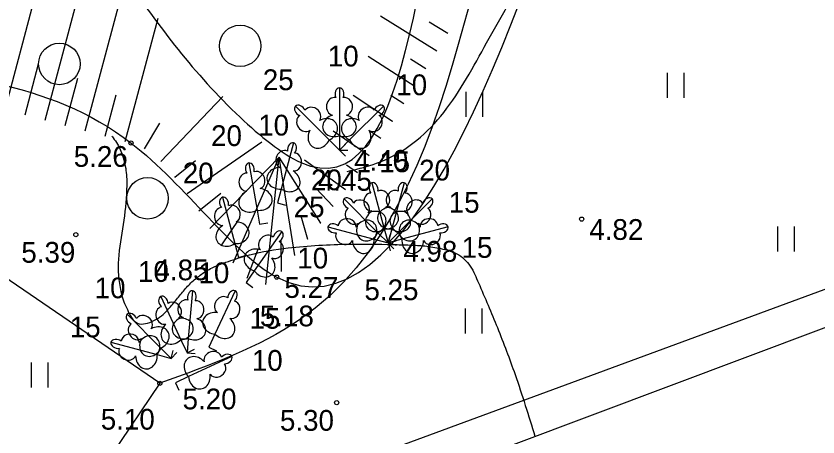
# Model space of a CAD drawing. Extents: x 519536 to 519949, y 326041 to 326519.
# Drawn here: x 519637.13 to 519656.46, y 326374.03 to 326384.17 of the extents above; entities that cross this region are included whole.
import ezdxf

# ---------------------------------------------------------------- set-up
doc = ezdxf.new("R2010")
doc.units = 0
for name, color, linetype in [('NORB_ZOGS_KOKA_####_#', 7, 'Continuous'), ('RAMI_UZMR_####_####_#', 7, 'Continuous'), ('RELJ_AATZ_####_TKST_#', 7, 'Continuous'), ('RELJ_ELEM_####_####_#', 7, 'Continuous'), ('RELJ_HORZ_PAMT_####_#', 7, 'Continuous'), ('RELJ_NOGA_####_####_#', 7, 'Continuous'), ('RELJ_NOGL_####_####_#', 7, 'Continuous'), ('ROBZ_UZMR_####_####_#', 7, 'Continuous'), ('TERT_DIAM_####_TKST_#', 7, 'Continuous'), ('TERT_ELEM_####_####_#', 7, 'Continuous'), ('TERT_KONT_####_####_#', 7, 'Continuous')]:
    doc.layers.add(name, color=color, linetype=linetype)

msp = doc.modelspace()

# ---------------------------------------------------------------- linework, layer by layer
at = {"layer": 'NORB_ZOGS_KOKA_####_#'}
msp.add_line((519640.6, 326375.326), (519637.78, 326371.172), dxfattribs=at)
at = {"layer": 'RAMI_UZMR_####_####_#'}
msp.add_lwpolyline([(519606.503, 326354.123), (519598.183, 326371.842), (519589.598, 326374.981), (519581.568, 326396.559), (519571.96, 326403.209), (519550.477, 326420.838), (519546.03, 326425.168), (519546.311, 326425.748), (519562.267, 326424.735), (519567.537, 326424.176), (519622.695, 326420.6), (519656.101, 326418.428), (519678.291, 326416.771), (519682.862, 326421.74), (519706.678, 326395.86), (519695.81, 326390.264), (519680.586, 326385.663), (519636.229, 326369.014), (519636.521, 326358.648)], dxfattribs=at)
at = {"layer": 'RELJ_ELEM_####_####_#'}
for centre in [(519639.907, 326381.113), (519650.767, 326379.28), (519638.576, 326378.905), (519643.418, 326377.883), (519640.6, 326375.326), (519644.864, 326374.858)]:
    msp.add_circle(centre, 0.05, dxfattribs=at)
at = {"layer": 'RELJ_HORZ_PAMT_####_#'}
for points in [[(519645.113, 326380.427), (519645.346, 326380.483), (519645.975, 326380.684), (519646.793, 326381.18), (519647.446, 326381.851), (519648.477, 326383.527), (519648.984, 326384.426), (519649.237, 326384.877), (519649.497, 326385.324), (519650.138, 326386.146), (519650.938, 326386.852), (519651.383, 326387.175), (519651.83, 326387.466), (519652.729, 326387.645), (519653.8, 326387.311), (519654.871, 326386.904), (519657.011, 326385.952), (519659.155, 326384.951), (519660.229, 326384.485), (519661.305, 326384.067), (519663.623, 326383.243), (519664.796, 326382.875), (519665.984, 326382.554), (519666.875, 326382.387), (519667.774, 326382.257), (519669.587, 326382.105), (519671.035, 326382.078)], [(519639.443, 326381.279), (519639.475, 326381.239), (519639.664, 326380.914), (519639.731, 326380.708), (519639.777, 326380.502), (519639.803, 326380.087), (519639.732, 326379.256), (519639.611, 326378.416), (519639.641, 326377.632), (519639.752, 326377.245), (519639.84, 326377.053), (519639.952, 326376.863), (519640.105, 326376.761), (519640.306, 326376.777), (519640.679, 326376.986), (519640.884, 326377.199), (519641.075, 326377.432), (519641.27, 326377.662), (519641.488, 326377.865), (519641.72, 326378.033)], [(519641.72, 326378.033), (519641.859, 326378.107), (519642.309, 326378.281), (519642.763, 326378.419), (519643.691, 326378.586), (519645.169, 326378.677), (519646.214, 326378.669), (519646.631, 326378.655)], [(519646.631, 326378.655), (519646.989, 326378.634), (519647.374, 326378.57), (519647.758, 326378.446), (519648.084, 326378.148), (519648.191, 326377.947), (519648.281, 326377.745), (519648.736, 326376.666), (519649.163, 326375.537), (519649.643, 326374.049)]]:
    msp.add_spline(points, degree=3, dxfattribs=at)
at = {"layer": 'RELJ_NOGA_####_####_#'}
for p, q in [((519636.87, 326381.924), (519637.996, 326386.141)), ((519637.836, 326381.666), (519638.886, 326385.6)), ((519638.802, 326381.408), (519639.777, 326385.059)), ((519639.768, 326381.15), (519640.56, 326384.116)), ((519647.28, 326383.323), (519645.917, 326384.164)), ((519647.541, 326383.75), (519647.095, 326384.022)), ((519647.541, 326383.75), (519647.541, 326383.75)), ((519647.28, 326383.323), (519647.279, 326383.324)), ((519646.75, 326382.475), (519645.619, 326383.194)), ((519647.016, 326382.898), (519646.643, 326383.132)), ((519637.353, 326381.795), (519637.679, 326383.018)), ((519647.016, 326382.898), (519647.016, 326382.899)), ((519638.319, 326381.537), (519638.623, 326382.675)), ((519646.75, 326382.475), (519646.749, 326382.476)), ((519639.285, 326381.279), (519639.55, 326382.272)), ((519646.207, 326381.635), (519645.257, 326382.261)), ((519646.48, 326382.054), (519646.171, 326382.254)), ((519640.626, 326380.665), (519642.12, 326382.232)), ((519646.48, 326382.054), (519646.48, 326382.054)), ((519637.353, 326381.795), (519637.353, 326381.795)), ((519637.836, 326381.666), (519637.836, 326381.667)), ((519638.319, 326381.537), (519638.319, 326381.537)), ((519640.233, 326380.972), (519640.6, 326381.591)), ((519646.207, 326381.635), (519646.207, 326381.636)), ((519638.802, 326381.408), (519638.802, 326381.409)), ((519645.65, 326380.805), (519644.78, 326381.401)), ((519645.931, 326381.219), (519645.663, 326381.399)), ((519639.285, 326381.279), (519639.285, 326381.279)), ((519639.768, 326381.15), (519639.768, 326381.151)), ((519641.261, 326379.894), (519643.055, 326381.143)), ((519645.931, 326381.219), (519645.93, 326381.219)), ((519640.233, 326380.972), (519640.233, 326380.972)), ((519641.808, 326379.057), (519643.479, 326380.769)), ((519642.366, 326378.228), (519643.479, 326380.769)), ((519643.157, 326377.704), (519643.479, 326380.769)), ((519643.856, 326378.401), (519643.479, 326380.769)), ((519644.478, 326379.185), (519643.479, 326380.769)), ((519645.65, 326380.805), (519645.649, 326380.805)), ((519640.626, 326380.665), (519640.627, 326380.665)), ((519640.961, 326380.294), (519641.46, 326380.694)), ((519645.075, 326379.987), (519644.084, 326380.7)), ((519645.365, 326380.394), (519645.096, 326380.582)), ((519645.365, 326380.394), (519645.365, 326380.394)), ((519640.961, 326380.294), (519640.962, 326380.295)), ((519644.364, 326380.026), (519644.779, 326379.584)), ((519645.075, 326379.987), (519645.074, 326379.988)), ((519641.261, 326379.894), (519641.262, 326379.895)), ((519641.539, 326379.479), (519642.07, 326379.906)), ((519644.779, 326379.584), (519644.779, 326379.584)), ((519641.539, 326379.479), (519641.539, 326379.479)), ((519644.171, 326378.79), (519644.008, 326379.349)), ((519642.078, 326378.637), (519642.527, 326379.301)), ((519644.478, 326379.185), (519644.477, 326379.185)), ((519641.808, 326379.057), (519641.809, 326379.058)), ((519643.535, 326378.018), (519643.527, 326378.784)), ((519644.171, 326378.79), (519644.17, 326378.791)), ((519642.078, 326378.637), (519642.079, 326378.637)), ((519642.702, 326377.859), (519642.981, 326378.583)), ((519643.856, 326378.401), (519643.856, 326378.402)), ((519642.366, 326378.228), (519642.367, 326378.228)), ((519643.535, 326378.018), (519643.535, 326378.019)), ((519642.702, 326377.859), (519642.702, 326377.859)), ((519643.157, 326377.704), (519643.157, 326377.705))]:
    msp.add_line(p, q, dxfattribs=at)
msp.add_spline([(519633.005, 326382.956), (519639.907, 326381.113), (519643.418, 326377.883), (519651.003, 326389.626), (519657.231, 326401.681), (519665.468, 326403.519), (519679.321, 326396.739), (519683.853, 326390.018), (519690.141, 326388.505), (519700.416, 326393.799)], degree=3, dxfattribs=at)
at = {"layer": 'RELJ_NOGL_####_####_#'}
msp.add_spline([(519639.78, 326385.057), (519642.535, 326381.732), (519643.997, 326380.646), (519647.881, 326390.255), (519656.007, 326401.958), (519665.234, 326406.681), (519680.265, 326397.515), (519685.71, 326391.104), (519688.362, 326390.219), (519691.184, 326390.387)], degree=3, dxfattribs=at)
at = {"layer": 'ROBZ_UZMR_####_####_#'}
msp.add_line((519634.774, 326369.546), (519706.067, 326395.801), dxfattribs=at)
at = {"layer": 'TERT_ELEM_####_####_#'}
for p, q in [((519652.838, 326382.204), (519652.838, 326382.804)), ((519653.238, 326382.204), (519653.238, 326382.804)), ((519647.982, 326381.744), (519647.982, 326382.344)), ((519648.382, 326381.744), (519648.382, 326382.344)), ((519644.931, 326381.288), (519644.931, 326380.941)), ((519644.686, 326381.186), (519644.931, 326380.941)), ((519645.176, 326381.186), (519644.931, 326380.941)), ((519644.931, 326380.941), (519645.072, 326381.082)), ((519644.931, 326380.941), (519645.131, 326380.941)), ((519644.931, 326380.941), (519645.072, 326380.8)), ((519643.526, 326380.005), (519643.436, 326379.67)), ((519643.436, 326379.67), (519643.629, 326379.618)), ((519642.944, 326379.497), (519643.004, 326379.155)), ((519643.004, 326379.155), (519643.201, 326379.19)), ((519646.011, 326379.043), (519646.101, 326378.708)), ((519646.191, 326379.043), (519646.101, 326378.708)), ((519655.5, 326378.5), (519655.5, 326379.1)), ((519655.9, 326378.5), (519655.9, 326379.1)), ((519645.766, 326378.798), (519646.101, 326378.708)), ((519645.856, 326378.953), (519646.101, 326378.708)), ((519646.346, 326378.953), (519646.101, 326378.708)), ((519646.101, 326378.708), (519646.153, 326378.901)), ((519646.101, 326378.708), (519646.242, 326378.849)), ((519646.436, 326378.798), (519646.101, 326378.708)), ((519642.408, 326378.692), (519642.498, 326378.357)), ((519646.101, 326378.708), (519646.294, 326378.76)), ((519646.101, 326378.708), (519646.294, 326378.656)), ((519646.101, 326378.708), (519646.242, 326378.567)), ((519646.101, 326378.708), (519646.153, 326378.515)), ((519642.498, 326378.357), (519642.691, 326378.409)), ((519642.878, 326378.036), (519642.679, 326377.752)), ((519642.679, 326377.752), (519642.843, 326377.637)), ((519647.968, 326376.525), (519647.968, 326377.125)), ((519648.368, 326376.525), (519648.368, 326377.125)), ((519641.929, 326376.51), (519641.782, 326376.196)), ((519641.109, 326376.374), (519641.256, 326376.06)), ((519641.286, 326376.406), (519641.256, 326376.06)), ((519640.627, 326376.172), (519640.872, 326375.927)), ((519640.872, 326375.927), (519640.924, 326376.12)), ((519640.872, 326375.927), (519641.013, 326376.068)), ((519641.256, 326376.06), (519641.437, 326376.145)), ((519641.782, 326376.196), (519641.963, 326376.111)), ((519640.537, 326376.017), (519640.872, 326375.927)), ((519641.256, 326376.06), (519641.455, 326376.043)), ((519637.509, 326375.224), (519637.509, 326375.824)), ((519637.909, 326375.224), (519637.909, 326375.824)), ((519641.29, 326375.487), (519640.976, 326375.34)), ((519640.976, 326375.34), (519641.061, 326375.159))]:
    msp.add_line(p, q, dxfattribs=at)
for points in [[(519644.931, 326382.441), (519644.931, 326381.288)], [(519645.021, 326382.209), (519645.02, 326382.21)], [(519643.87, 326382.002), (519644.686, 326381.186)], [(519644.098, 326381.901), (519644.097, 326381.901)], [(519645.992, 326382.002), (519645.176, 326381.186)], [(519645.891, 326381.774), (519645.891, 326381.775)], [(519643.824, 326381.119), (519643.526, 326380.005)], [(519643.851, 326380.871), (519643.85, 326380.872)], [(519642.744, 326380.632), (519642.944, 326379.497)], [(519642.872, 326380.419), (519642.871, 326380.42)], [(519645.713, 326380.157), (519646.011, 326379.043)], [(519646.489, 326380.157), (519646.191, 326379.043)], [(519645.859, 326379.956), (519645.858, 326379.956)], [(519642.11, 326379.806), (519642.408, 326378.692)], [(519645.04, 326379.769), (519645.856, 326378.953)], [(519647.162, 326379.769), (519646.346, 326378.953)], [(519646.516, 326379.909), (519646.515, 326379.91)], [(519642.256, 326379.605), (519642.255, 326379.605)], [(519645.268, 326379.668), (519645.267, 326379.668)], [(519647.061, 326379.541), (519647.061, 326379.542)], [(519643.539, 326378.981), (519642.878, 326378.036)], [(519644.652, 326379.096), (519645.766, 326378.798)], [(519644.9, 326379.123), (519644.899, 326379.122)], [(519647.55, 326379.096), (519646.436, 326378.798)], [(519647.349, 326378.95), (519647.349, 326378.951)], [(519643.479, 326378.739), (519643.479, 326378.74)], [(519640.622, 326377.419), (519641.109, 326376.374)], [(519641.387, 326377.554), (519641.286, 326376.406)], [(519642.416, 326377.555), (519641.929, 326376.51)], [(519640.801, 326377.247), (519640.8, 326377.247)], [(519641.456, 326377.315), (519641.455, 326377.316)], [(519642.399, 326377.307), (519642.398, 326377.308)], [(519639.811, 326376.988), (519640.627, 326376.172)], [(519640.039, 326376.887), (519640.038, 326376.887)], [(519639.423, 326376.315), (519640.537, 326376.017)], [(519639.671, 326376.342), (519639.67, 326376.341)], [(519642.335, 326375.974), (519641.29, 326375.487)], [(519642.163, 326375.795), (519642.163, 326375.796)]]:
    msp.add_lwpolyline(points, dxfattribs=at)
for centre in [(519642.537, 326383.453), (519638.179, 326383.018), (519640.304, 326379.781)]:
    msp.add_circle(centre, 0.5, dxfattribs=at)
for centre, major_axis, ratio, start_param, end_param in [((519644.931, 326382.291), (0, -0.15), 0.707107, 3.14537, 5.287485), ((519644.931, 326382.291), (0, -0.15), 0.707107, 0.995701, 3.137816), ((519644.803, 326381.996), (-0.039, -0.212), 0.861323, 3.141593, 6.283185), ((519645.059, 326381.996), (0.039, -0.212), 0.861323, 0, 3.141593), ((519643.977, 326381.896), (0.106, -0.106), 0.707107, 3.14537, 5.287485), ((519643.976, 326381.895), (0.106, -0.106), 0.707107, 0.995701, 3.137816), ((519644.276, 326381.778), (0.178, -0.123), 0.861323, 6.283185, 9.424778), ((519645.586, 326381.778), (-0.178, -0.123), 0.861323, 3.141593, 6.283185), ((519645.886, 326381.895), (-0.106, -0.106), 0.707107, 3.14537, 5.287485), ((519645.885, 326381.896), (-0.106, -0.106), 0.707107, 0.995701, 3.137816), ((519644.094, 326381.596), (0.123, -0.178), 0.861323, 3.141593, 6.283185), ((519644.575, 326381.424), (-0.284, -0.15), 0.814445, 1.531171, 4.712389), ((519644.841, 326381.534), (0.307, 0.095), 0.814445, 1.570796, 4.752015), ((519645.021, 326381.534), (-0.307, 0.095), 0.814445, 1.531171, 4.712389), ((519645.287, 326381.424), (0.284, -0.15), 0.814445, 1.570796, 4.752015), ((519645.768, 326381.596), (-0.123, -0.178), 0.861323, 6.283185, 9.424778), ((519644.448, 326381.297), (0.15, 0.284), 0.814445, 1.570796, 4.752015), ((519645.414, 326381.297), (-0.15, 0.284), 0.814445, 1.531171, 4.712389), ((519643.786, 326380.974), (-0.039, -0.145), 0.707107, 3.14537, 5.287485), ((519643.785, 326380.974), (-0.039, -0.145), 0.707107, 0.995701, 3.137816), ((519643.585, 326380.722), (-0.092, -0.195), 0.861323, 3.141593, 6.283185), ((519643.833, 326380.656), (-0.018, -0.215), 0.861323, 0, 3.141593), ((519642.77, 326380.485), (0.026, -0.148), 0.707107, 3.14537, 5.287485), ((519642.769, 326380.484), (0.026, -0.148), 0.707107, 0.995701, 3.137816), ((519643.503, 326380.266), (0.321, 0.012), 0.814445, 1.570796, 4.752015), ((519642.694, 326380.172), (-0.001, -0.216), 0.861323, 3.141593, 6.283185), ((519642.947, 326380.216), (0.075, -0.202), 0.861323, 0, 3.141593), ((519643.676, 326380.22), (-0.272, 0.171), 0.814445, 1.531171, 4.712389), ((519645.752, 326380.012), (0.039, -0.145), 0.707107, 3.14537, 5.287485), ((519645.751, 326380.012), (0.039, -0.145), 0.707107, 0.995701, 3.137816), ((519646.451, 326380.012), (-0.039, -0.145), 0.707107, 3.14537, 5.287485), ((519646.45, 326380.012), (-0.039, -0.145), 0.707107, 0.995701, 3.137816), ((519642.813, 326379.723), (0.286, 0.147), 0.814445, 1.570796, 4.752015), ((519642.989, 326379.754), (-0.319, 0.04), 0.814445, 1.531171, 4.712389), ((519645.952, 326379.76), (0.092, -0.195), 0.861323, 0, 3.141593), ((519646.25, 326379.76), (-0.092, -0.195), 0.861323, 3.141593, 6.283185), ((519642.149, 326379.661), (0.039, -0.145), 0.707107, 3.14537, 5.287485), ((519642.148, 326379.661), (0.039, -0.145), 0.707107, 0.995701, 3.137816), ((519645.147, 326379.663), (0.106, -0.106), 0.707107, 3.14537, 5.287485), ((519645.146, 326379.662), (0.106, -0.106), 0.707107, 0.995701, 3.137816), ((519645.446, 326379.545), (0.178, -0.123), 0.861323, 6.283185, 9.424778), ((519645.704, 326379.694), (0.018, -0.215), 0.861323, 3.141593, 6.283185), ((519646.498, 326379.694), (-0.018, -0.215), 0.861323, 0, 3.141593), ((519646.756, 326379.545), (-0.178, -0.123), 0.861323, 3.141593, 6.283185), ((519647.056, 326379.662), (-0.106, -0.106), 0.707107, 3.14537, 5.287485), ((519647.055, 326379.663), (-0.106, -0.106), 0.707107, 0.995701, 3.137816), ((519642.101, 326379.343), (0.018, -0.215), 0.861323, 3.141593, 6.283185), ((519642.349, 326379.409), (0.092, -0.195), 0.861323, 0, 3.141593), ((519645.264, 326379.363), (0.123, -0.178), 0.861323, 3.141593, 6.283185), ((519646.168, 326379.304), (0.321, 0.012), 0.814445, 1.570796, 4.752015), ((519646.034, 326379.304), (-0.321, 0.012), 0.814445, 1.531171, 4.712389), ((519646.938, 326379.363), (-0.123, -0.178), 0.861323, 6.283185, 9.424778), ((519645.861, 326379.258), (0.272, 0.171), 0.814445, 1.570796, 4.752015), ((519645.745, 326379.191), (-0.284, -0.15), 0.814445, 1.531171, 4.712389), ((519646.457, 326379.191), (0.284, -0.15), 0.814445, 1.570796, 4.752015), ((519646.341, 326379.258), (-0.272, 0.171), 0.814445, 1.531171, 4.712389), ((519642.431, 326378.953), (-0.321, 0.012), 0.814445, 1.531171, 4.712389), ((519644.797, 326379.057), (0.145, -0.039), 0.707107, 0.995701, 3.137816), ((519645.115, 326379.105), (0.215, -0.018), 0.861323, 0, 3.141593), ((519645.618, 326379.064), (0.15, 0.284), 0.814445, 1.570796, 4.752015), ((519645.551, 326378.948), (-0.171, -0.272), 0.814445, 1.531171, 4.712389), ((519646.584, 326379.064), (-0.15, 0.284), 0.814445, 1.531171, 4.712389), ((519646.651, 326378.948), (0.171, -0.272), 0.814445, 1.570796, 4.752015), ((519647.087, 326379.105), (-0.215, -0.018), 0.861323, 3.141593, 6.283185), ((519647.405, 326379.057), (-0.145, -0.039), 0.707107, 3.14537, 5.287485), ((519642.258, 326378.907), (0.272, 0.171), 0.814445, 1.570796, 4.752015), ((519643.454, 326378.858), (-0.086, -0.123), 0.707107, 3.14537, 5.287485), ((519643.453, 326378.858), (-0.086, -0.123), 0.707107, 0.995701, 3.137816), ((519644.797, 326379.058), (0.145, -0.039), 0.707107, 3.14537, 5.287485), ((519647.405, 326379.058), (-0.145, -0.039), 0.707107, 0.995701, 3.137816), ((519643.179, 326378.69), (-0.154, -0.152), 0.861323, 3.141593, 6.283185), ((519645.049, 326378.857), (0.195, -0.092), 0.861323, 3.141593, 6.283185), ((519645.505, 326378.775), (-0.012, 0.321), 0.814445, 1.570796, 4.752015), ((519646.697, 326378.775), (0.012, 0.321), 0.814445, 1.531171, 4.712389), ((519647.153, 326378.857), (-0.195, -0.092), 0.861323, 0, 3.141593), ((519642.946, 326378.289), (0.306, -0.098), 0.814445, 1.570796, 4.752015), ((519643.389, 326378.543), (-0.09, -0.196), 0.861323, 6.283185, 9.424778), ((519643.092, 326378.186), (-0.197, 0.254), 0.814445, 1.531171, 4.712389), ((519640.686, 326377.284), (0.063, -0.136), 0.707107, 3.14537, 5.287485), ((519640.685, 326377.283), (0.063, -0.136), 0.707107, 0.995701, 3.137816), ((519641.374, 326377.405), (-0.013, -0.149), 0.707107, 3.14537, 5.287485), ((519641.373, 326377.405), (-0.013, -0.149), 0.707107, 0.995701, 3.137816), ((519642.112, 326377.207), (-0.125, -0.176), 0.861323, 3.141593, 6.283185), ((519642.353, 326377.419), (-0.063, -0.136), 0.707107, 3.14537, 5.287485), ((519642.352, 326377.42), (-0.063, -0.136), 0.707107, 0.995701, 3.137816), ((519640.926, 326377.071), (0.125, -0.176), 0.861323, 0, 3.141593), ((519641.22, 326377.122), (-0.057, -0.208), 0.861323, 3.141593, 6.283185), ((519641.476, 326377.1), (0.02, -0.215), 0.861323, 0, 3.141593), ((519642.344, 326377.098), (-0.055, -0.209), 0.861323, 0, 3.141593), ((519640.694, 326376.962), (0.055, -0.209), 0.861323, 3.141593, 6.283185), ((519641.951, 326376.771), (0.318, -0.043), 0.814445, 1.570796, 4.752015), ((519639.918, 326376.882), (0.106, -0.106), 0.707107, 3.14537, 5.287485), ((519639.917, 326376.881), (0.106, -0.106), 0.707107, 0.995701, 3.137816), ((519640.217, 326376.764), (0.178, -0.123), 0.861323, 6.283185, 9.424778), ((519641.218, 326376.658), (0.314, 0.068), 0.814445, 1.570796, 4.752015), ((519641.087, 326376.635), (-0.318, -0.043), 0.814445, 1.531171, 4.712389), ((519641.397, 326376.643), (-0.297, 0.121), 0.814445, 1.531171, 4.712389), ((519642.114, 326376.696), (-0.238, 0.216), 0.814445, 1.531171, 4.712389), ((519640.035, 326376.582), (0.123, -0.178), 0.861323, 3.141593, 6.283185), ((519640.516, 326376.41), (-0.284, -0.15), 0.814445, 1.531171, 4.712389), ((519640.924, 326376.56), (0.238, 0.216), 0.814445, 1.570796, 4.752015), ((519639.886, 326376.324), (0.215, -0.018), 0.861323, 0, 3.141593), ((519640.322, 326376.167), (-0.171, -0.272), 0.814445, 1.531171, 4.712389), ((519639.568, 326376.277), (0.145, -0.039), 0.707107, 3.14537, 5.287485), ((519639.568, 326376.276), (0.145, -0.039), 0.707107, 0.995701, 3.137816), ((519640.389, 326376.283), (0.15, 0.284), 0.814445, 1.570796, 4.752015), ((519639.82, 326376.076), (0.195, -0.092), 0.861323, 3.141593, 6.283185), ((519641.878, 326375.902), (-0.209, -0.055), 0.861323, 3.141593, 6.283185), ((519640.276, 326375.994), (-0.012, 0.321), 0.814445, 1.570796, 4.752015), ((519641.476, 326375.672), (0.216, -0.238), 0.814445, 1.570796, 4.752015), ((519642.2, 326375.91), (-0.136, -0.063), 0.707107, 3.14537, 5.287485), ((519642.199, 326375.911), (-0.136, -0.063), 0.707107, 0.995701, 3.137816), ((519641.987, 326375.67), (-0.176, -0.125), 0.861323, 0, 3.141593), ((519641.551, 326375.509), (-0.043, 0.318), 0.814445, 1.531171, 4.712389)]:
    msp.add_ellipse(centre, major_axis=major_axis, ratio=ratio, start_param=start_param, end_param=end_param, dxfattribs=at)
at = {"layer": 'TERT_KONT_####_####_#'}
msp.add_line((519640.6, 326375.326), (519631.246, 326381.713), dxfattribs=at)
for points in [[(519617.458, 326408.853), (519614.406, 326408.421), (519613.425, 326408.287), (519612.935, 326408.209), (519612.691, 326408.164), (519612.446, 326408.112), (519612.195, 326407.934), (519612.05, 326407.611), (519611.983, 326407.242), (519611.962, 326406.931), (519612.022, 326406.495), (519612.212, 326406.065), (519612.91, 326405.218), (519615.027, 326403.551), (519617.072, 326401.861), (519617.681, 326400.987), (519617.806, 326400.081), (519617.632, 326399.669), (519617.334, 326399.244), (519617.028, 326398.808), (519616.827, 326398.364), (519616.67, 326397.679), (519616.553, 326396.945), (519616.589, 326395.862), (519616.631, 326395.694), (519616.687, 326395.531), (519617.235, 326394.482), (519617.976, 326393.521), (519619.807, 326391.769), (519621.72, 326390.081), (519622.563, 326389.2), (519623.255, 326388.264), (519623.656, 326387.3), (519623.912, 326386.211), (519624.184, 326385.124), (519624.631, 326384.166), (519625.267, 326383.787), (519626.155, 326383.728), (519627.059, 326383.732), (519627.444, 326383.678), (519627.746, 326383.543), (519628.081, 326382.913), (519628.235, 326381.979), (519628.375, 326381.094), (519628.493, 326380.782), (519628.671, 326380.615), (519628.921, 326380.569), (519629.257, 326380.576), (519630.055, 326380.748), (519630.805, 326381.127), (519631.246, 326381.713), (519631.293, 326381.95), (519631.303, 326382.19), (519631.26, 326382.673), (519631.202, 326383.156), (519631.2, 326383.513), (519631.215, 326383.631), (519631.33, 326384.243), (519631.478, 326384.85), (519631.668, 326385.449), (519631.908, 326386.037), (519633.023, 326386.993), (519634.679, 326387.43), (519636.274, 326387.881), (519637.205, 326388.884), (519637.297, 326389.248), (519637.376, 326389.616), (519637.495, 326390.362), (519637.585, 326391.875), (519637.494, 326393.388), (519637.245, 326394.868), (519636.946, 326396.104), (519636.617, 326397.338), (519636.287, 326398.572), (519635.986, 326399.809), (519635.636, 326401.492), (519635.353, 326403.202), (519635.177, 326404.912), (519635.14, 326405.758), (519635.137, 326406.178), (519635.144, 326406.594), (519635.346, 326407.323), (519635.839, 326407.935), (519637.329, 326408.962), (519638.871, 326409.997), (519639.43, 326410.617), (519639.723, 326411.359), (519641.003, 326419.41)], [(519657.62, 326398.43), (519650.463, 326391.501), (519643.964, 326376.852), (519640.6, 326375.326)]]:
    msp.add_spline(points, degree=3, dxfattribs=at)

# ---------------------------------------------------------------- texts
at = {"layer": 'RELJ_AATZ_####_TKST_#'}
for s, p in [(' 5.26', (519638.34, 326380.539)), (' 4.40', (519645.099, 326380.444)), ('4.45', (519644.41, 326379.964)), (' 4.82', (519650.767, 326378.78)), (' 5.39', (519637.076, 326378.23)), (' 4.98', (519646.283, 326378.254)), ('4.85', (519640.472, 326377.808)), (' 5.27', (519643.418, 326377.383)), ('5.25', (519645.533, 326377.328)), ('5.18', (519643.012, 326376.698)), (' 5.20', (519640.963, 326374.699)), ('5.10', (519639.177, 326374.21)), (' 5.30', (519643.31, 326374.183))]:
    msp.add_text(s, height=0.5, dxfattribs=at).set_placement(p)
at = {"layer": 'TERT_DIAM_####_TKST_#'}
for s, p in [('10', (519644.649, 326382.957)), ('25', (519643.083, 326382.386)), ('10', (519646.3, 326382.265)), ('10', (519642.972, 326381.293)), ('20', (519641.836, 326381.04)), ('15', (519645.888, 326380.41)), ('20', (519646.851, 326380.21)), ('20', (519641.154, 326380.14)), ('20', (519644.245, 326379.976)), ('15', (519647.564, 326379.434)), ('25', (519643.827, 326379.324)), ('15', (519647.874, 326378.348)), ('10', (519643.914, 326378.091)), ('10', (519640.074, 326377.768)), ('10', (519641.532, 326377.737)), ('10', (519639.03, 326377.374)), ('15', (519642.762, 326376.64)), ('15', (519638.43, 326376.433)), ('10', (519642.818, 326375.628))]:
    msp.add_text(s, height=0.5, dxfattribs=at).set_placement(p)

doc.saveas('drawing.dxf')
